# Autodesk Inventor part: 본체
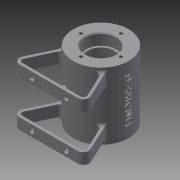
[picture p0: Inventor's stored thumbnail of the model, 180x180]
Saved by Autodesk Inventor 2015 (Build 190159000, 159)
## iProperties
Created: 2021-12
Part Number: 본체
Material: 일반
Document SubType Name: Modeling
Designer: pc-04
Density: 1 g/cm^3
Appearance: 기본값
Mass: 115.147 g
Surface Area: 363.055 cm^2
Volume: 115.147 cm^3
Author: pc-04
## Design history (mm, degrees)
sketch "스케치1"
  geometry: L1 (0, 23.783)-(0, -24.591); L2 (22.482, 0)-(-20.059, 0); L3 (16, 35)-(16, 23); L4 (16, 23)-(14, 23); L5 (14, 23)-(14, 21); L6 (14, 21)-(21, 21); L7 (21, 21)-(21, -21); L8 (21, -21)-(14, -21); L9 (14, -21)-(14, -23); L10 (14, -23)-(16, -23); L11 (16, -23)-(16, -35); L12 (16, -35)-(29, -35); L13 (29, -35)-(29, 35); L14 (29, 35)-(16, 35); 1 further point
  constraints: 28 end point, 10 perpendicular, 3 vertical, 2 point on line, 1 horizontal, 2 other
  dimensions: "d0" = 58 diameter of L13 L1; "d1" = 32 diameter of L3 L1; "d2" = 28 diameter of L5 L1; "d3" = 70 distance of L12.end L13.end; "d4" = 12 distance of L3.start L3.end; "d5" = 2 distance of L4.end L5.end; "d6" = 42 diameter of L7 L1; "d7" = 28 diameter of L9 L1; "d8" = 32 diameter of L11 L1; "d9" = 12 distance of L10.end L11.end
revolve "회전1" sketch "스케치1" stored, may be unused: angle "d10" = 90 deg
node "작업 평면1"
sketch "스케치2"
  geometry: L1 (0, 0)-(0, -60.703); L2 (-40.334, 0)-(38.661, 0); L3 (-40, -55)-(40, -55); L4 (40, -55)-(21.814, -16); L5 (-40, -55)-(-21.814, -16); L6 (-21.814, -16)-(21.814, -16); L7 (35.291, -52)-(-35.291, -52); L8 (-35.291, -52)-(-19.903, -19); L9 (-19.903, -19)-(19.903, -19); L10 (19.903, -19)-(35.291, -52)
  constraints: 20 end point, 2 horizontal, 1 point on line, 1 symmetric about line, 1 vertical, 3 other
  dimensions: "d12" = 65 deg angle of L3 L5; "d13" = 65 deg angle of L3 L4; "d14" = 39 vertical distance of L3.start L5.end; "d15" = 39 vertical distance of L3.end L4.end; "d16" = 55 distance between parallel lines of L2 L3; "d17" = 80 distance of L3.start L3.end; "d18" = 3 distance between parallel lines of L3 L7
extrude "돌출1" join sketch "스케치2" distance "d19" = 12; taper "d20" = 0 deg
fillet "모깎기1" dims "d21" = 6
fillet "모깎기2" dims "d22" = 3
fillet "모깎기3" dims "d23" = 3
sketch "스케치4"
  geometry: L1 (30.582, 11.573)-(30.582, -76.988); L2 (70.724, -30)-(-9.956, -30); C1 r 3 at (48.582, -6); C2 r 3 at (12.582, -6); C3 r 3 at (48.582, -54); C4 r 3 at (12.582, -54); 1 further point
  constraints: 4 centre point, 4 end point, 3 equal radius, 2 point on line, 2 symmetric about line, 1 horizontal, 1 horizontal alignment, 1 vertical, 1 vertical alignment
  dimensions: "d24" = 48 distance of C3.centre C1.centre; "d25" = 36 distance of C1.centre C2.centre; "d26" = 6 diameter of C2
extrude "돌출2" cut sketch "스케치4" distance "d27" = 12; taper "d28" = 0 deg
sketch "스케치5"
  geometry: L1 (0, 0)-(0, -68.401); L2 (-13.163, -18.621)-(-16.583, -28.018); L3 (-10.945, -30.07)-(-16.583, -28.018); L4 (-7.524, -20.673)-(-13.163, -18.621); L5 (0, 0)-(-22.158, -60.878); L6 (-7.524, -20.673)-(-10.945, -30.07)
  constraints: 12 end point, 2 point on line, 1 collinear, 1 perpendicular, 1 vertical
  dimensions: "d32" = 32 distance from line of L1.start L3; "d34" = 20 deg angle of L1 L5; "d35" = 6 distance between parallel lines of L5 L2; "d36" = 10 distance between parallel lines of L3 L4
revolve "회전2" sketch "스케치5" stored, may be unused: angle "d37" = 90 deg
sketch "스케치6"
  geometry: 4 further points
  constraints: 3 coincident
hole "구멍1" sketch "스케치6" at (0, 0) diameter "d38" = 4.917; stored, may be unused: countersink angle "d42" = 90 deg, drill point angle "d44" = 118 deg; dims "d39" = 16, "d40" = 4, "d41" = 2, "d43" = 21.1
fillet "모깎기4" dims "d45" = 1
sketch "스케치7" dims "d46" = 42
  geometry: L1 (0, 0)-(0, 21); 2 further points
  constraints: 2 coincident, 2 end point, 1 vertical, 1 vertical alignment, 2 other
hole "구멍2" sketch "스케치7" at (0, 21) diameter "d47" = 3.242; stored, may be unused: countersink angle "d51" = 90 deg, drill point angle "d53" = 118 deg; dims "d48" = 8, "d49" = 4, "d50" = 2, "d52" = 10
node "작업 평면2"
sketch "스케치8"
  geometry: C1 r 5 at (0, 0); 1 further point
  constraints: 1 centre point, 1 coincident
  dimensions: "d58" = 10 diameter of C1
extrude "돌출3" join sketch "스케치8" stored distance "d59" = 12; taper "d60" = 0 deg
sketch "스케치9"
  geometry: C1 r 1.5 at (0, 0); 2 further points
  constraints: 2 coincident, 1 centre point
  dimensions: "d68" = 3 diameter of C1
hole "구멍3" sketch "스케치9" diameter "d61" = 4.917; stored, may be unused: countersink angle "d65" = 90 deg, drill point angle "d67" = 118 deg; dims "d62" = 6, "d63" = 4, "d64" = 2, "d66" = 8
extrude "돌출4" cut sketch "스케치9" distance "d69" = 20; taper "d70" = 0 deg
fillet "모깎기5" dims "d71" = 0.3
fillet "모깎기6" dims "d72" = 3
chamfer "모따기1" distance "d73" = 1; stored, may be unused: second distance "d74" = 2, angle "d75" = 45 deg
fillet "모깎기7" dims "d76" = 1
node "작업 평면3"
sketch "스케치10"
  geometry: L1 (18.759, 8.024)-(18.759, -7.807); L2 (18.759, -7.807)-(-19.626, -7.807); L3 (-19.626, -7.807)-(-19.626, 8.024); L4 (-19.626, 8.024)-(18.759, 8.024); 1 further point
  constraints: 2 other
extrude "돌출5" join sketch "스케치10" stored distance "d78" = 20; taper "d79" = 0 deg
fillet "모깎기8" dims "d80" = 3
fillet "모깎기9" dims "d81" = 0.5
node "솔리드1"
mirror "대칭1"
mirror "대칭2"
pattern_circular "원형 패턴1" dims angle "d55" = 360 deg
mirror "대칭3"
other parameters: "d57" = 32
